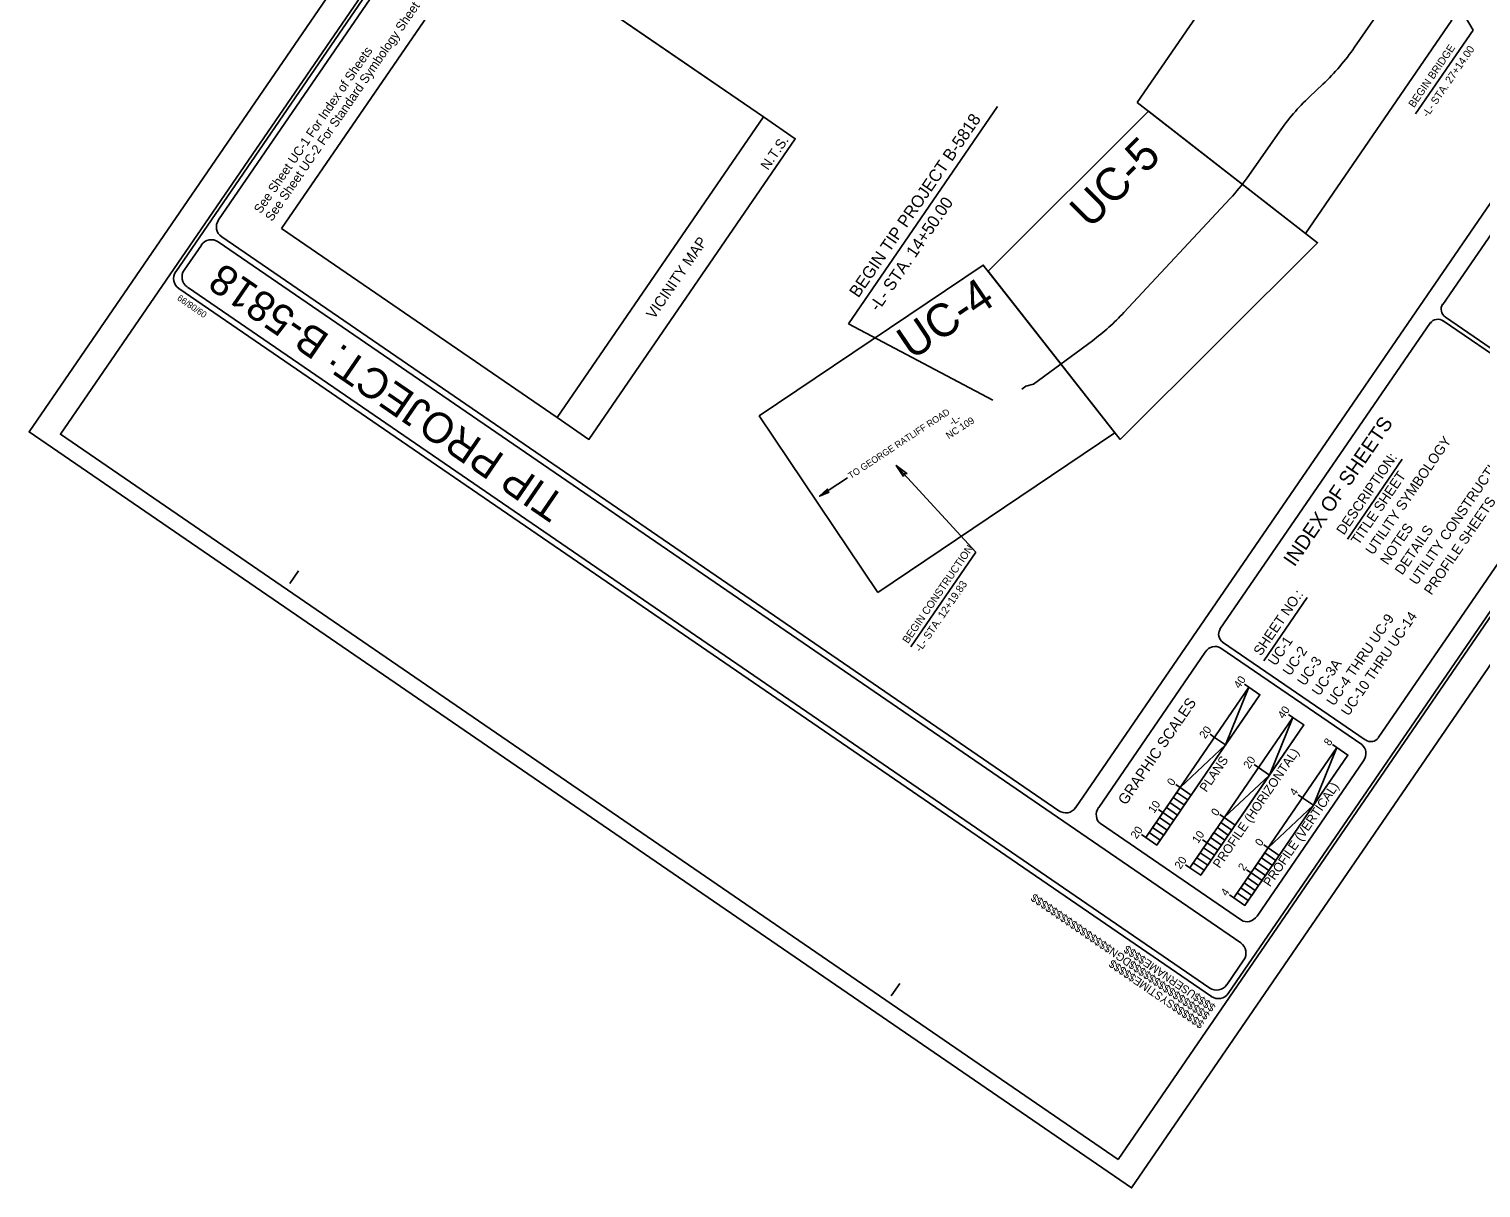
# Model space of a CAD drawing. Extents: x 1638787 to 1643250, y 391480 to 396306.
# Drawn here: x 1638787 to 1641654, y 391480 to 393769 of the extents above; entities that cross this region are included whole.
import ezdxf

# ---------------------------------------------------------------- set-up
doc = ezdxf.new("R2010")
doc.units = 0
for name, color, linetype in [('Old_Level_1', 7, 'Continuous'), ('Old_Level_32', 7, 'Continuous'), ('Old_Level_38', 7, 'Continuous'), ('Prop 8 In Water Line (St)', 7, 'Continuous'), ('Prop Terminator CELL', 7, 'Continuous'), ('Sheet Plan Layout CELL', 7, 'Continuous'), ('Sheet Plot Border Inside CELL', 7, 'Continuous'), ('Sheet Plot Border Outside CELL', 7, 'Continuous'), ('Sheet Title CELL', 7, 'Continuous'), ('UC Title Plan Sheet 34 CELL', 7, 'Continuous')]:
    doc.layers.add(name, color=color, linetype=linetype)

msp = doc.modelspace()

# ---------------------------------------------------------------- linework, layer by layer
at = {"layer": 'Old_Level_1'}
for p, q in [((1641638.6, 393766.5), (1641514, 393981.5)), ((1641525.2, 393601.2), (1641638.6, 393766.5)), ((1640699.2, 393615.6), (1640405.2, 393186.8)), ((1640405.2, 393186.8), (1640690.5, 393035.7)), ((1640499.5, 392907.2), (1640656.5, 392736.1)), ((1640348.3, 392846.2), (1640403.4, 392882.5)), ((1640528.2, 392549), (1640656.5, 392736.1))]:
    msp.add_line(p, q, dxfattribs=at)
at = {"layer": 'Old_Level_32'}
for points in [[(1639285.7, 393374.7), (1639692.9, 393968.5), (1640237.3, 393595.3), (1639830.1, 393001.5)], [(1639285.7, 393374.7), (1639668.6, 393933), (1639851, 393807.9), (1639875.3, 393843.4), (1640237.3, 393595.3), (1639830.1, 393001.5)], [(1639830.1, 393001.5), (1640237.3, 393595.3), (1640300.1, 393552.1), (1639892.9, 392958.3)]]:
    msp.add_lwpolyline(points, close=True, dxfattribs=at)
at = {"layer": 'Prop 8 In Water Line (St)'}
for p, q in [((1641404.6, 393733.1), (1641521.3, 393902.5)), ((1641315.7, 393635.1), (1641341.9, 393659.8)), ((1641192.2, 393475.3), (1641255.4, 393565.3)), ((1640949.2, 393209.1), (1641159.2, 393434.2)), ((1640770.9, 393067.4), (1640886.8, 393153.4)), ((1640747.5, 393057.6), (1640755.5, 393063.5)), ((1640755.5, 393063.5), (1640770.9, 393067.4))]:
    msp.add_line(p, q, dxfattribs=at)
for centre, start, end in [((1641025.8, 393994), 313.4038, 325.4432), ((1641631.8, 393300.9), 133.4038, 144.9038), ((1640817.7, 393742.4), 317.9334, 324.4983), ((1640612.8, 393522.9), 306.5623, 316.9969)]:
    msp.add_arc(centre, 460, start, end, dxfattribs=at)
at = {"layer": 'Prop Terminator CELL'}
for points in [[(1640513.8, 392885.1), (1640499.5, 392907.2), (1640520.5, 392891.1), (1640514.9, 392890.4)], [(1640367.1, 392854.4), (1640348.3, 392846.2), (1640363.3, 392860.4), (1640363.1, 392855.9)]]:
    msp.add_lwpolyline(points, close=True, dxfattribs=at)
at = {"layer": 'Sheet Plan Layout CELL'}
for points in [[(1640975.6, 393623.7), (1641250.2, 394024.1), (1641596.6, 393786.6), (1641307.7, 393365.2)], [(1640941.9, 392958), (1641331.5, 393346.7), (1640997.5, 393606.7), (1640680.8, 393290.8)], [(1640463.5, 392656.4), (1640229.1, 393004.9), (1640671.3, 393302.8), (1640931.3, 392971.5)]]:
    msp.add_lwpolyline(points, close=True, dxfattribs=at)
at = {"layer": 'Sheet Plot Border Inside CELL'}
msp.add_lwpolyline([(1640937.7, 391536.4), (1643199.6, 394834.9), (1641111.3, 396267), (1638849.3, 392968.5)], close=True, dxfattribs=at)
at = {"layer": 'Sheet Plot Border Outside CELL'}
msp.add_lwpolyline([(1641072.9, 396306.4), (1638787.2, 392973.3), (1640964.4, 391480.2), (1643250.2, 394813.4)], close=True, dxfattribs=at)
at = {"layer": 'UC Title Plan Sheet 34 CELL'}
for p, q in [((1640853.8, 392231.2), (1642781.2, 395041.9)), ((1641578.7, 393225.1), (1641939.9, 393750.4)), ((1641179.8, 391964), (1639160.9, 393348.5)), ((1640820.4, 392225), (1639167.7, 393358.4)), ((1641138.6, 392583.5), (1641554.4, 393189.6)), ((1641860.6, 392999.9), (1641579.6, 393192.7)), ((1641865.3, 393006.8), (1641584.2, 393199.6)), ((1641451.4, 392369.3), (1641866.7, 392975.1)), ((1641390.6, 392761.3), (1641498.8, 392919.2)), ((1639302.2, 392673.9), (1639319.2, 392698.7)), ((1639302.2, 392673.9), (1639319.2, 392698.7)), ((1641225.4, 392521.5), (1641311.1, 392646.1)), ((1641140.6, 392546.3), (1641418.7, 392355.7)), ((1641425.6, 392365.4), (1641144.1, 392558.1)), ((1640899.3, 392231.7), (1641109.7, 392538.5)), ((1641196, 392469.1), (1640992.4, 392172.2)), ((1641196, 392469.1), (1641187.3, 392475.1)), ((1641217.7, 392454.2), (1641196, 392469.1)), ((1641014.1, 392157.3), (1641217.7, 392454.2)), ((1641282.9, 392409.5), (1641079.3, 392112.6)), ((1641282.9, 392409.5), (1641079.3, 392112.6)), ((1641282.9, 392409.5), (1641274.2, 392415.5)), ((1641282.9, 392409.5), (1641274.2, 392415.5)), ((1641304.6, 392394.6), (1641282.9, 392409.5)), ((1641101, 392097.7), (1641304.6, 392394.6)), ((1641128.1, 392370.1), (1641119.4, 392376.1)), ((1641128.1, 392370.1), (1641149.8, 392355.2)), ((1641369.8, 392349.9), (1641166.2, 392053)), ((1641369.8, 392349.9), (1641166.2, 392053)), ((1641369.8, 392349.9), (1641166.2, 392053)), ((1641369.8, 392349.9), (1641361.1, 392355.9)), ((1641369.8, 392349.9), (1641361.1, 392355.9)), ((1641369.8, 392349.9), (1641361.1, 392355.9)), ((1641391.5, 392335), (1641369.8, 392349.9)), ((1641187.9, 392038.1), (1641391.5, 392335)), ((1641215, 392310.5), (1641206.3, 392316.5)), ((1641215, 392310.5), (1641206.3, 392316.5)), ((1641215, 392310.5), (1641236.7, 392295.6)), ((1641060.3, 392271.1), (1641051.6, 392277.1)), ((1641301.9, 392250.9), (1641293.2, 392256.9)), ((1641301.9, 392250.9), (1641293.2, 392256.9)), ((1641301.9, 392250.9), (1641293.2, 392256.9)), ((1641026.3, 392221.7), (1641017.6, 392227.6)), ((1641039.9, 392241.5), (1641061.6, 392226.6)), ((1641301.9, 392250.9), (1641323.6, 392236)), ((1641181.2, 392009.3), (1640903.1, 392200)), ((1641147.1, 392211.6), (1641138.5, 392217.5)), ((1641147.1, 392211.6), (1641138.5, 392217.5)), ((1640992.4, 392172.2), (1640983.7, 392178.1)), ((1640983.7, 392178.1), (1640983.7, 392178.1)), ((1640992.4, 392172.2), (1641014.1, 392157.3)), ((1640992.4, 392172.2), (1640992.4, 392172.2)), ((1641126.8, 392181.9), (1641148.5, 392167)), ((1641113.2, 392162.1), (1641104.5, 392168)), ((1641113.2, 392162.1), (1641104.5, 392168)), ((1641234, 392152), (1641225.4, 392158)), ((1641234, 392152), (1641225.4, 392158)), ((1641234, 392152), (1641225.4, 392158)), ((1641079.3, 392112.6), (1641070.6, 392118.6)), ((1641079.3, 392112.6), (1641070.6, 392118.6)), ((1641070.6, 392118.6), (1641070.6, 392118.6)), ((1641079.3, 392112.6), (1641101, 392097.7)), ((1641079.3, 392112.6), (1641079.3, 392112.6)), ((1641079.3, 392112.6), (1641079.3, 392112.6)), ((1641213.7, 392122.3), (1641235.4, 392107.4)), ((1641200.1, 392102.5), (1641191.4, 392108.4)), ((1641200.1, 392102.5), (1641191.4, 392108.4)), ((1641200.1, 392102.5), (1641191.4, 392108.4)), ((1641166.2, 392053), (1641157.5, 392059)), ((1641166.2, 392053), (1641157.5, 392059)), ((1641166.2, 392053), (1641157.5, 392059)), ((1641157.5, 392059), (1641157.5, 392059)), ((1641166.2, 392053), (1641187.9, 392038.1)), ((1641166.2, 392053), (1641166.2, 392053)), ((1641166.2, 392053), (1641166.2, 392053)), ((1641166.2, 392053), (1641166.2, 392053)), ((1640489.8, 391859.5), (1640506.7, 391884.3)), ((1640489.8, 391859.5), (1640506.7, 391884.3)), ((1641141.6, 391844.7), (1641141.6, 391844.7)), ((1641141.6, 391844.7), (1641141.6, 391844.7)), ((1641141.6, 391844.7), (1641141.6, 391844.7)), ((1641141.6, 391844.7), (1641141.6, 391844.7))]:
    msp.add_line(p, q, dxfattribs=at)
for points in [[(1641085.8, 396219.1), (1639076.9, 393289.6)], [(1641088.9, 396202.4), (1639161.5, 393391.8)], [(1641155.2, 391864.5), (1643164, 394793.9)], [(1639127.6, 393342.2), (1639093.6, 393292.8)], [(1639099.8, 393259.4), (1641118.7, 391875)], [(1639083.1, 393256.3), (1641121.8, 391858.3)], [(1639083.1, 393256.3), (1641121.8, 391858.3)], [(1641212.1, 392017.1), (1641422.5, 392324)], [(1641152.1, 391881.2), (1641186, 391930.7)]]:
    msp.add_lwpolyline(points, dxfattribs=at)
for points in [[(1641196, 392469.1), (1641149.8, 392355.2), (1641217.7, 392454.2)], [(1641282.9, 392409.5), (1641236.7, 392295.6), (1641304.6, 392394.6)], [(1641060.3, 392271.1), (1641149.8, 392355.2), (1641082, 392256.2)], [(1641369.8, 392349.9), (1641323.6, 392236), (1641391.5, 392335)], [(1641147.1, 392211.6), (1641236.7, 392295.6), (1641168.9, 392196.7)], [(1641046.7, 392251.4), (1641053.5, 392261.3), (1641075.2, 392246.4), (1641068.4, 392236.5)], [(1641033.1, 392231.6), (1641039.9, 392241.5), (1641061.6, 392226.6), (1641054.8, 392216.7)], [(1641234, 392152), (1641323.6, 392236), (1641255.8, 392137.1)], [(1641005.9, 392192), (1641012.8, 392201.9), (1641034.5, 392187), (1641027.7, 392177.1)], [(1641019.5, 392211.8), (1641026.3, 392221.7), (1641048, 392206.8), (1641041.2, 392196.9)], [(1641133.6, 392191.8), (1641140.3, 392201.7), (1641162.1, 392186.8), (1641155.3, 392176.9)], [(1640992.4, 392172.2), (1640999.2, 392182.1), (1641020.9, 392167.2), (1641014.1, 392157.3)], [(1641120, 392172), (1641126.8, 392181.9), (1641148.5, 392167), (1641141.7, 392157.1)], [(1641092.8, 392132.4), (1641099.6, 392142.3), (1641121.4, 392127.4), (1641114.6, 392117.5)], [(1641106.4, 392152.2), (1641113.2, 392162.1), (1641134.9, 392147.2), (1641128.2, 392137.3)], [(1641220.5, 392132.2), (1641227.2, 392142.1), (1641249, 392127.2), (1641242.2, 392117.3)], [(1641079.3, 392112.6), (1641086.1, 392122.5), (1641107.8, 392107.6), (1641101, 392097.7)], [(1641206.9, 392112.4), (1641213.7, 392122.3), (1641235.4, 392107.4), (1641228.6, 392097.5)], [(1641179.7, 392072.8), (1641186.5, 392082.7), (1641208.2, 392067.8), (1641201.5, 392057.9)], [(1641193.3, 392092.6), (1641200.1, 392102.5), (1641221.8, 392087.6), (1641215, 392077.7)], [(1641166.2, 392053), (1641173, 392062.9), (1641194.7, 392048), (1641187.9, 392038.1)]]:
    msp.add_lwpolyline(points, close=True, dxfattribs=at)
for centre, start, end in [((1639181.2, 393378.2), 145.5597, 235.5597), ((1639147.2, 393328.8), 55.5597, 145.5597), ((1639096.6, 393276.2), 145.5597, 235.5597), ((1639113.3, 393279.3), 145.5597, 235.5597), ((1640833.9, 392244.9), 235.5597, 325.5597), ((1641166.1, 391944.3), 325.5597, 55.5597), ((1641132.2, 391894.8), 235.5597, 325.5597), ((1641135.3, 391878.1), 235.5597, 325.5597)]:
    msp.add_arc(centre, 24, start, end, dxfattribs=at)
for centre, major_axis, ratio, start_param, end_param in [((1641594.1, 393214.8), (-15.6, 10.7), 0.941469, 6.282374, 7.853553), ((1641570, 393177.6), (15.6, -10.7), 0.941469, 1.570196, 3.141423), ((1641154.7, 392572.5), (-15.6, 10.7), 0.941469, 6.283016, 7.853558), ((1641127, 392526.6), (-13.6, -19.8), 0.877963, 3.141593, 4.712389), ((1641405, 392335.9), (13.6, 19.8), 0.877963, 4.712389, 6.283185), ((1641436.2, 392379.8), (-15.6, 10.7), 0.941469, 1.570372, 3.141423), ((1640916.6, 392219.8), (-13.6, -19.8), 0.877963, 4.712389, 6.283185), ((1641194.6, 392029.1), (-13.6, -19.8), 0.877963, 0, 1.570796)]:
    msp.add_ellipse(centre, major_axis=major_axis, ratio=ratio, start_param=start_param, end_param=end_param, dxfattribs=at)

# ---------------------------------------------------------------- texts
at = {"layer": 'Old_Level_1'}
for s, height, rotation, p in [('BEGIN BRIDGE', 15, 55.5597, (1641522, 393612.4)), ('-L- STA. 27+14.00', 15, 55.5597, (1641549.2, 393593.7)), ('BEGIN TIP PROJECT B-5818', 24, 55.5597, (1640424.8, 393236.7)), ('UC-5', 64.8, 44.9279, (1640882.1, 393372.5)), ('-L- STA. 14+50.00', 24, 55.5597, (1640464.4, 393209.6)), ('UC-4', 64.8, 33.9342, (1640530.1, 393114.1)), ('TO GEORGE RATLIFF ROAD', 13, 33.363, (1640409.9, 392879.8)), ('NC 109', 13.71, 32.9762, (1640603.2, 392958.5)), ('-L-', 13.71, 32.9762, (1640609.9, 392985)), ('BEGIN CONSTRUCTION', 15, 55.5597, (1640522.8, 392554.3)), ('-L- STA. 12+19.83', 15, 55.5597, (1640547.5, 392537.4))]:
    msp.add_text(s, height=height, rotation=rotation, dxfattribs=at).set_placement(p)
at = {"layer": 'Old_Level_38'}
for s, height, p in [('N.T.S.', 19.5, (1640246.3, 393488.8)), ('VICINITY MAP', 21, (1640021.5, 393194.7))]:
    msp.add_text(s, height=height, rotation=55.5597, dxfattribs=at).set_placement(p)
at = {"layer": 'Sheet Title CELL'}
for s, p in [('See Sheet UC-2 For Standard Symbology Sheet', (1639266.8, 393387.7)), ('See Sheet UC-1 For Index of Sheets', (1639244.6, 393403))]:
    msp.add_text(s, height=18, rotation=55.5597, dxfattribs=at).set_placement(p)
at = {"layer": 'UC Title Plan Sheet 34 CELL'}
for s, height, rotation, p in [('TIP PROJECT: B-5818', 60, 145.5597, (1639850.4, 392842.6)), ('09/08/99', 12.6, 145.5597, (1639139.8, 393208)), ('UTILITY CONSTRUCTION SHEETS', 19.779, 55.5455, (1641527.6, 392669.5)), ('INDEX OF SHEETS', 28.749, 55.5455, (1641285.7, 392705.5)), ('UTILITY SYMBOLOGY', 19.779, 55.5455, (1641441.1, 392728.9)), ('DESCRIPTION:', 19.779, 55.5455, (1641383.4, 392768.4)), ('TITLE SHEET', 19.779, 55.5455, (1641412.3, 392748.6)), ('PROFILE SHEETS', 19.779, 55.5455, (1641556.4, 392649.7)), ('NOTES', 19.78, 55.5455, (1641469.9, 392709.1)), ('DETAILS', 19.78, 55.5455, (1641498.8, 392689.3)), ('SHEET NO.:', 19.78, 55.5455, (1641219.7, 392529.6)), ('UC-4 THRU UC-9', 19.779, 55.5455, (1641363.9, 392430.7)), ('UC-10 THRU UC-14', 19.779, 55.5455, (1641392.7, 392410.9)), ('UC-1', 19.78, 55.5455, (1641248.6, 392509.9)), ('UC-2', 19.78, 55.5455, (1641277.4, 392490.1)), ('UC-3', 19.78, 55.5455, (1641306.2, 392470.3)), ('UC-3A ', 19.78, 55.5455, (1641335.1, 392450.5)), ('40', 15.8, 55.5597, (1641177.5, 392465.1)), ('GRAPHIC SCALES', 21.071, 55.5597, (1640953.1, 392234.9)), ('40', 15.8, 55.5597, (1641264.4, 392405.6)), ('20', 15.8, 55.5597, (1641109.7, 392366.1)), ('PROFILE (HORIZONTAL)', 17.91, 55.5597, (1641138.1, 392110.2)), ('8', 15.8, 55.5597, (1641355.4, 392351.8)), ('PLANS', 17.91, 55.5597, (1641111.8, 392260.6)), ('20', 15.8, 55.5597, (1641196.6, 392306.6)), ('0', 15.8, 55.5597, (1641045.8, 392273)), ('PROFILE (VERTICAL)', 17.91, 55.5597, (1641237.6, 392073.7)), ('4', 15.8, 55.5597, (1641287.8, 392253.3)), ('10', 15.8, 55.5597, (1641008.8, 392219)), ('0', 15.8, 55.5597, (1641132.7, 392213.5)), ('0', 15.8, 55.5597, (1641133, 392213.3)), ('20', 15.8, 55.5597, (1640974, 392168.2)), ('10', 15.8, 55.5597, (1641095.7, 392159.4)), ('0', 15.8, 55.5597, (1641219.6, 392153.9)), ('0', 15.8, 55.5597, (1641219.9, 392153.7)), ('0', 15.8, 55.5597, (1641219.9, 392153.7)), ('20', 15.8, 55.5597, (1641060.8, 392108.6)), ('2', 15.8, 55.5597, (1641186.2, 392105.1)), ('$$$$$$$$$$$$$$$$DGN$$$$$$$$$$$$$$$$', 15.75, 145.5597, (1641120.1, 391823.9)), ('4', 15.8, 55.5597, (1641152, 392055.3)), ('$$$$USERNAME$$$$', 15.75, 145.5597, (1641131.6, 391839.9)), ('$$$$$$SYSTIME$$$$$', 15.75, 145.5597, (1641109, 391806.8))]:
    msp.add_text(s, height=height, rotation=rotation, dxfattribs=at).set_placement(p)

doc.saveas('drawing.dxf')
